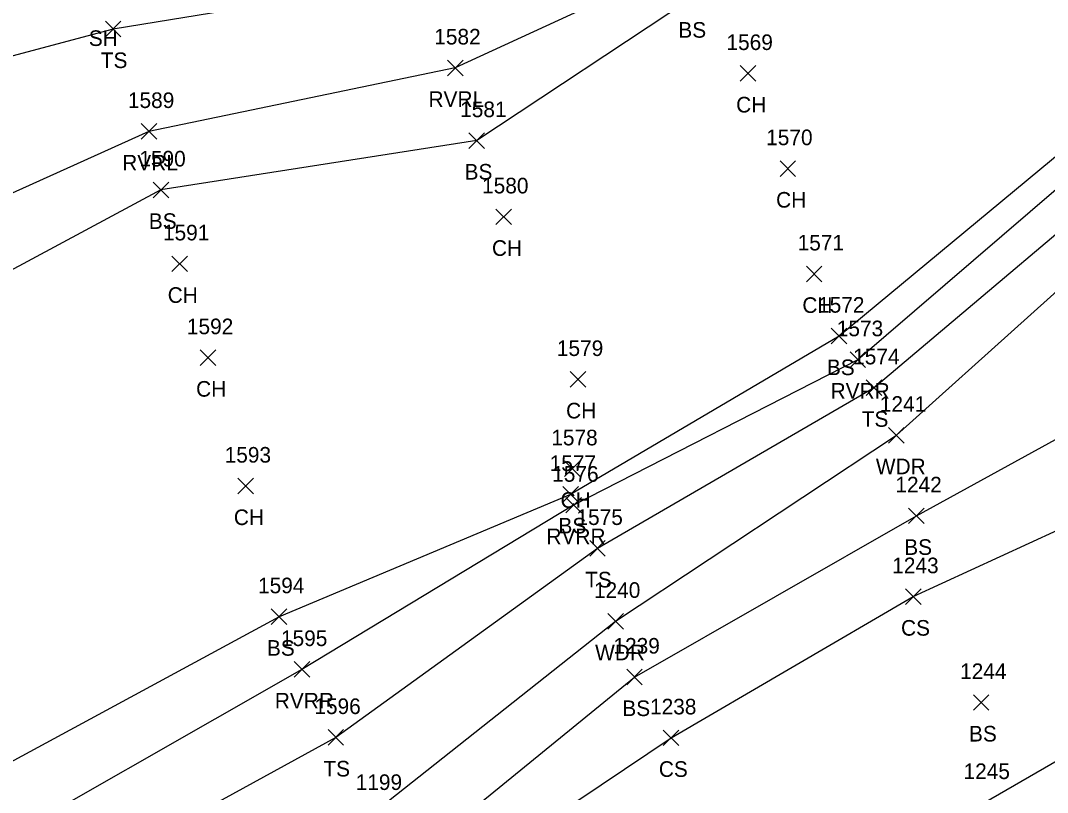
# Model space of a CAD drawing. Extents: x 1443064 to 1445163, y 544063 to 544655.
# Drawn here: x 1443332.1 to 1443463.7, y 544302.3 to 544401.2 of the extents above; entities that cross this region are included whole.
import ezdxf

# ---------------------------------------------------------------- set-up
doc = ezdxf.new("R2010")
doc.units = 0
for name, color, linetype in [('L_A', 7, 'Continuous'), ('L_I', 7, 'Continuous'), ('L_TIC', 7, 'Continuous'), ('LAWA', 7, 'Continuous'), ('LAWE', 7, 'Continuous'), ('LELB', 7, 'Continuous')]:
    doc.layers.add(name, color=color, linetype=linetype)

msp = doc.modelspace()

# ---------------------------------------------------------------- linework, layer by layer
at = {"layer": 'L_TIC'}
for points in [[(1443342.94, 544399.11), (1443344.94, 544401.11)], [(1443344.94, 544399.11), (1443342.94, 544401.11)], [(1443386.79, 544394.13), (1443388.79, 544396.13)], [(1443388.79, 544394.13), (1443386.79, 544396.13)], [(1443424.31, 544393.42), (1443426.31, 544395.42)], [(1443426.31, 544393.42), (1443424.31, 544395.42)], [(1443347.53, 544385.99), (1443349.53, 544387.99)], [(1443349.53, 544385.99), (1443347.53, 544387.99)], [(1443389.54, 544384.82), (1443391.54, 544386.82)], [(1443391.54, 544384.82), (1443389.54, 544386.82)], [(1443429.43, 544381.23), (1443431.43, 544383.23)], [(1443431.43, 544381.23), (1443429.43, 544383.23)], [(1443349.07, 544378.5), (1443351.07, 544380.5)], [(1443351.07, 544378.5), (1443349.07, 544380.5)], [(1443393.01, 544375.05), (1443395.01, 544377.05)], [(1443395.01, 544375.05), (1443393.01, 544377.05)], [(1443351.45, 544369.03), (1443353.45, 544371.03)], [(1443353.45, 544369.03), (1443351.45, 544371.03)], [(1443432.8, 544367.74), (1443434.8, 544369.74)], [(1443434.8, 544367.74), (1443432.8, 544369.74)], [(1443435.99, 544359.77), (1443437.99, 544361.77)], [(1443437.99, 544359.77), (1443435.99, 544361.77)], [(1443355.08, 544357.01), (1443357.08, 544359.01)], [(1443357.08, 544357.01), (1443355.08, 544359.01)], [(1443438.4, 544356.75), (1443440.4, 544358.75)], [(1443440.4, 544356.75), (1443438.4, 544358.75)], [(1443402.52, 544354.22), (1443404.52, 544356.22)], [(1443404.52, 544354.22), (1443402.52, 544356.22)], [(1443440.49, 544353.15), (1443442.49, 544355.15)], [(1443442.49, 544353.15), (1443440.49, 544355.15)], [(1443443.34, 544347.07), (1443445.34, 544349.07)], [(1443445.34, 544347.07), (1443443.34, 544349.07)], [(1443401.79, 544342.77), (1443403.79, 544344.77)], [(1443403.79, 544342.77), (1443401.79, 544344.77)], [(1443359.92, 544340.56), (1443361.92, 544342.56)], [(1443361.92, 544340.56), (1443359.92, 544342.56)], [(1443401.58, 544339.48), (1443403.58, 544341.48)], [(1443403.58, 544339.48), (1443401.58, 544341.48)], [(1443401.97, 544338.11), (1443403.97, 544340.11)], [(1443403.97, 544338.11), (1443401.97, 544340.11)], [(1443445.9, 544336.74), (1443447.9, 544338.74)], [(1443447.9, 544336.74), (1443445.9, 544338.74)], [(1443405.03, 544332.57), (1443407.03, 544334.57)], [(1443407.03, 544332.57), (1443405.03, 544334.57)], [(1443445.5, 544326.39), (1443447.5, 544328.39)], [(1443447.5, 544326.39), (1443445.5, 544328.39)], [(1443364.21, 544323.82), (1443366.21, 544325.82)], [(1443366.21, 544323.82), (1443364.21, 544325.82)], [(1443407.35, 544323.23), (1443409.35, 544325.23)], [(1443409.35, 544323.23), (1443407.35, 544325.23)], [(1443367.14, 544317.06), (1443369.14, 544319.06)], [(1443369.14, 544317.06), (1443367.14, 544319.06)], [(1443409.77, 544316.09), (1443411.77, 544318.09)], [(1443411.77, 544316.09), (1443409.77, 544318.09)], [(1443454.21, 544312.83), (1443456.21, 544314.83)], [(1443456.21, 544312.83), (1443454.21, 544314.83)], [(1443371.48, 544308.35), (1443373.48, 544310.35)], [(1443373.48, 544308.35), (1443371.48, 544310.35)], [(1443414.45, 544308.3), (1443416.45, 544310.3)], [(1443416.45, 544308.3), (1443414.45, 544310.3)]]:
    msp.add_lwpolyline(points, dxfattribs=at)
at = {"layer": 'LAWA'}
msp.add_lwpolyline([(1443328.33, 544272.01), (1443354.38, 544286), (1443377.17, 544299.62), (1443408.35, 544324.23), (1443444.34, 544348.07), (1443478.82, 544379), (1443505.14, 544393.05), (1443523.9, 544408.72), (1443558.4, 544420.46), (1443603.2, 544442.99), (1443623.82, 544449.76), (1443648.97, 544490.11)], dxfattribs=at)
at = {"layer": 'LAWE'}
for points in [[(1443607.93, 544544.59), (1443575.82, 544505.29), (1443541.97, 544483.15), (1443496.37, 544455.19), (1443456.91, 544428.49), (1443417.34, 544408.78), (1443387.79, 544395.13), (1443348.53, 544386.99), (1443298.57, 544364.46), (1443252.13, 544357.4), (1443220.15, 544339.73), (1443174.97, 544320.79), (1443137.84, 544313.37), (1443113.71, 544316.35), (1443080.05, 544317.62)], [(1443627.73, 544516.96), (1443602.93, 544465.06), (1443560.09, 544445.87), (1443514.11, 544419.1), (1443476.33, 544389.4), (1443439.4, 544357.75), (1443402.97, 544339.11), (1443368.14, 544318.06), (1443323.16, 544292.42), (1443281.44, 544273.46), (1443240.37, 544261.14), (1443193.33, 544260.65), (1443164.34, 544237.83), (1443139.78, 544220.74), (1443138.28, 544217.17), (1443133.77, 544210.32), (1443100.97, 544202.05)]]:
    msp.add_lwpolyline(points, dxfattribs=at)
at = {"layer": 'LELB'}
for points in [[(1443603.25, 544552.64), (1443570.25, 544515.22), (1443538.04, 544489.77), (1443492.2, 544462.32), (1443452.76, 544437.41), (1443412.31, 544422.78), (1443382, 544406.31), (1443343.94, 544400.11), (1443289.24, 544385.53), (1443246.49, 544373.38), (1443215.47, 544352.77), (1443170.81, 544332.99), (1443133.49, 544325.06), (1443111.8, 544326.37), (1443077.06, 544328.43)], [(1443612.67, 544538.44), (1443580.84, 544497.81), (1443546.17, 544475.2), (1443499.76, 544448.59), (1443458.28, 544425.05), (1443417.94, 544404), (1443390.54, 544385.82), (1443350.07, 544379.5), (1443300.95, 544353.17), (1443254.38, 544348.68), (1443222.6, 544329.72), (1443175.23, 544317.99), (1443139.34, 544307.97), (1443114.07, 544306.7), (1443079.96, 544313.03)], [(1443623.25, 544521.72), (1443599.67, 544467.52), (1443557.8, 544451.16), (1443512.32, 544424.47), (1443473.97, 544391.39), (1443436.99, 544360.77), (1443402.58, 544340.48), (1443365.21, 544324.82), (1443319.81, 544300.23), (1443279.76, 544280.29), (1443239.01, 544265.94), (1443191.15, 544266.77), (1443161, 544250.15), (1443130.5, 544221.16), (1443098.72, 544215.41)], [(1443630.6, 544513.66), (1443606.19, 544459.79), (1443563.47, 544440.26), (1443516.58, 544414.23), (1443479.57, 544386.27), (1443441.49, 544354.15), (1443406.03, 544333.57), (1443372.48, 544309.35), (1443326.54, 544284.19), (1443284.74, 544264.48), (1443242.9, 544256.57), (1443195.74, 544252.68), (1443182.88, 544237.49), (1443172.34, 544228.16)], [(1443348.08, 544245.71), (1443367.85, 544273.1), (1443385.57, 544289.21), (1443415.45, 544309.3), (1443446.5, 544327.39), (1443476.22, 544341.09), (1443487.16, 544364.37), (1443505.14, 544393.05)], [(1443343.36, 544234.64), (1443341.34, 544245.28), (1443362.31, 544278.45), (1443382.08, 544293.73), (1443410.77, 544317.09), (1443446.9, 544337.74), (1443471.29, 544351.11), (1443478.82, 544379)], [(1443361.65, 544240.04), (1443365.6, 544252.15), (1443382.87, 544266.28), (1443423.93, 544281.08), (1443455.64, 544301.02), (1443483.09, 544316.84), (1443502.95, 544323.75), (1443492.91, 544341.29), (1443492.61, 544354.67)]]:
    msp.add_lwpolyline(points, dxfattribs=at)

# ---------------------------------------------------------------- texts
at = {"layer": 'L_A'}
for s, p in [('BS', (1443416.39, 544399)), ('SH', (1443340.82, 544397.94)), ('TS', (1443342.35, 544395.11)), ('RVRL', (1443384.36, 544390.13)), ('CH', (1443423.8, 544389.42)), ('RVRL', (1443345.1, 544381.99)), ('BS', (1443388.99, 544380.82)), ('CH', (1443428.92, 544377.23)), ('BS', (1443348.51, 544374.5)), ('CH', (1443392.5, 544371.05)), ('CH', (1443350.93, 544365.03)), ('CH', (1443432.29, 544363.74)), ('BS', (1443435.43, 544355.77)), ('CH', (1443354.57, 544353.01)), ('RVRR', (1443435.91, 544352.75)), ('CH', (1443402, 544350.22)), ('TS', (1443439.9, 544349.15)), ('WDR', (1443441.71, 544343.07)), ('CH', (1443401.28, 544338.77)), ('CH', (1443359.41, 544336.56)), ('BS', (1443401.02, 544335.48)), ('RVRR', (1443399.48, 544334.11)), ('BS', (1443445.35, 544332.74)), ('TS', (1443404.44, 544328.57)), ('CS', (1443444.94, 544322.39)), ('BS', (1443363.65, 544319.82)), ('WDR', (1443405.72, 544319.23)), ('RVRR', (1443364.66, 544313.06)), ('BS', (1443409.21, 544312.09)), ('BS', (1443453.65, 544308.83)), ('TS', (1443370.89, 544304.35)), ('CS', (1443413.89, 544304.3))]:
    msp.add_text(s, height=2, dxfattribs=at).set_placement(p)
at = {"layer": 'L_I'}
for s, p in [('1582', (1443385.1, 544398.13)), ('1569', (1443422.56, 544397.42)), ('1589', (1443345.83, 544389.99)), ('1581', (1443388.42, 544388.82)), ('1570', (1443427.65, 544385.23)), ('1590', (1443347.29, 544382.5)), ('1580', (1443391.23, 544379.05)), ('1591', (1443350.32, 544373.03)), ('1571', (1443431.68, 544371.74)), ('1572', (1443434.3, 544363.77)), ('1592', (1443353.39, 544361.01)), ('1573', (1443436.7, 544360.75)), ('1579', (1443400.82, 544358.22)), ('1574', (1443438.8, 544357.15)), ('1241', (1443442.22, 544351.07)), ('1578', (1443400.1, 544346.77)), ('1593', (1443358.23, 544344.56)), ('1577', (1443399.89, 544343.48)), ('1576', (1443400.22, 544342.11)), ('1242', (1443444.21, 544340.74)), ('1575', (1443403.33, 544336.57)), ('1243', (1443443.81, 544330.39)), ('1594', (1443362.51, 544327.82)), ('1240', (1443405.57, 544327.23)), ('1595', (1443365.45, 544321.06)), ('1239', (1443408.07, 544320.09)), ('1244', (1443452.51, 544316.83)), ('1596', (1443369.73, 544312.35)), ('1238', (1443412.76, 544312.3)), ('1245', (1443452.95, 544304.02)), ('1199', (1443375.03, 544302.62))]:
    msp.add_text(s, height=2, dxfattribs=at).set_placement(p)

doc.saveas('drawing.dxf')
